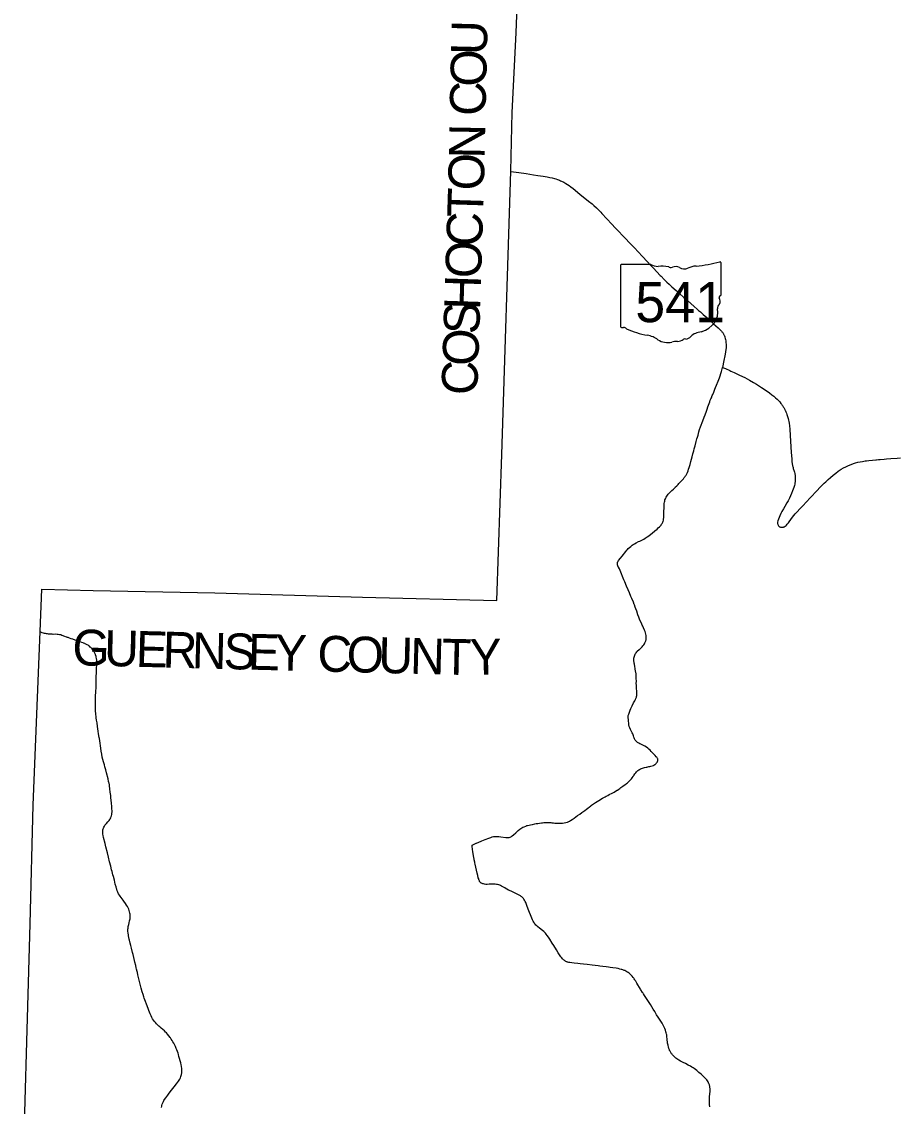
# Model space of a CAD drawing. Extents: x 2125567 to 2397567, y 653347 to 829347.
# Drawn here: x 2186978 to 2211403, y 770418 to 800656 of the extents above; entities that cross this region are included whole.
import ezdxf

# ---------------------------------------------------------------- set-up
doc = ezdxf.new("R2010")
doc.units = 0
for name, color, linetype in [('GM_X_County', 7, 'Continuous'), ('GM_X_County_Text', 7, 'Continuous'), ('GM_X_State_Location', 7, 'Continuous'), ('GM_X_State_Route', 7, 'Continuous'), ('GM_X_State_Shield', 7, 'Continuous')]:
    doc.layers.add(name, color=color, linetype=linetype)

msp = doc.modelspace()

# ---------------------------------------------------------------- linework, layer by layer
at = {"layer": 'GM_X_County'}
msp.add_lwpolyline([(2186978, 767293), (2187218, 775508), (2187296, 778812), (2187489, 783655), (2187543, 784833), (2188969, 784801), (2192356, 784732), (2196471, 784613), (2200213, 784515), (2200352, 788594), (2200607, 796487), (2200640, 798126), (2200752, 800346), (2200989, 806420)], dxfattribs=at)
at = {"layer": 'GM_X_State_Route'}
for points in [[(2200608, 796484), (2200827, 796452), (2201034, 796420), (2201242, 796389), (2201359, 796372), (2201512, 796349), (2201618, 796331), (2201696, 796316), (2201757, 796302), (2201820, 796284), (2201861, 796272), (2201905, 796257), (2201934, 796247), (2201963, 796235), (2201995, 796221), (2202023, 796208), (2202082, 796178), (2202137, 796147), (2202187, 796117), (2202234, 796086), (2202279, 796053), (2202347, 796001), (2202533, 795850), (2202772, 795655), (2202871, 795574), (2202918, 795533), (2202990, 795465), (2203039, 795417), (2203085, 795371), (2203110, 795345), (2203146, 795307), (2203420, 795015), (2203517, 794912), (2203626, 794798), (2203713, 794705), (2203811, 794599), (2203901, 794503), (2204048, 794349), (2204150, 794242), (2204271, 794113), (2204404, 793972), (2204500, 793868), (2204578, 793784), (2204675, 793682), (2204769, 793582), (2204792, 793558), (2204879, 793469), (2204956, 793393), (2205020, 793335), (2205026, 793329), (2205094, 793267), (2205212, 793163), (2205305, 793080), (2205426, 792970), (2205527, 792881), (2205618, 792801), (2205712, 792718), (2205796, 792645), (2205840, 792606), (2205887, 792565), (2205965, 792496), (2206069, 792405), (2206169, 792315), (2206256, 792235), (2206385, 792119), (2206394, 792110), (2206430, 792075), (2206464, 792040), (2206477, 792026), (2206488, 792012), (2206500, 791997), (2206510, 791983), (2206519, 791970), (2206528, 791956), (2206536, 791943), (2206542, 791929), (2206550, 791913), (2206558, 791896), (2206561, 791888)], [(2206561, 791888), (2206565, 791880), (2206571, 791862), (2206581, 791828), (2206589, 791799), (2206596, 791756), (2206602, 791711), (2206605, 791658), (2206605, 791633), (2206605, 791608), (2206603, 791566), (2206597, 791513), (2206589, 791454), (2206577, 791390), (2206530, 791165), (2206511, 791059), (2206504, 791019)], [(2204051, 784396), (2204046, 784409), (2204022, 784470), (2203977, 784572), (2203950, 784635), (2203911, 784733), (2203876, 784818), (2203831, 784920), (2203780, 785037), (2203757, 785095), (2203721, 785186), (2203693, 785262), (2203671, 785313), (2203652, 785354), (2203630, 785399), (2203606, 785445), (2203600, 785455), (2203596, 785464), (2203592, 785474), (2203588, 785483), (2203585, 785493), (2203584, 785499), (2203581, 785509), (2203579, 785522), (2203578, 785530), (2203577, 785542), (2203577, 785550), (2203578, 785561), (2203580, 785572), (2203581, 785578), (2203583, 785586), (2203586, 785592), (2203590, 785602), (2203594, 785610), (2203600, 785620), (2203609, 785632), (2203665, 785701), (2203705, 785751), (2203744, 785801), (2203770, 785835), (2203810, 785890), (2203838, 785925), (2203856, 785945), (2203879, 785966), (2203909, 785994), (2203948, 786026), (2203988, 786058), (2204018, 786079), (2204054, 786101), (2204103, 786127), (2204163, 786161), (2204200, 786178), (2204253, 786203), (2204312, 786234), (2204346, 786254), (2204373, 786272), (2204403, 786291), (2204451, 786326), (2204505, 786371), (2204542, 786401), (2204617, 786460), (2204680, 786512), (2204716, 786543), (2204745, 786570), (2204769, 786596), (2204791, 786622), (2204807, 786646), (2204823, 786670), (2204832, 786684), (2204839, 786699), (2204845, 786714), (2204850, 786726), (2204858, 786757), (2204864, 786789), (2204870, 786831), (2204871, 786875), (2204873, 786929), (2204874, 786992), (2204875, 787115), (2204879, 787185), (2204883, 787221), (2204888, 787259), (2204894, 787291), (2204902, 787322), (2204912, 787352), (2204924, 787379), (2204937, 787405), (2204952, 787429), (2204969, 787453), (2204992, 787480), (2205019, 787509), (2205096, 787585), (2205136, 787623), (2205146, 787632), (2205157, 787644), (2205174, 787659), (2205190, 787675), (2205230, 787714), (2205249, 787732), (2205271, 787756), (2205291, 787778), (2205309, 787797), (2205318, 787806), (2205369, 787861), (2205393, 787888), (2205416, 787916), (2205441, 787947), (2205460, 787974), (2205473, 787993), (2205481, 788005), (2205488, 788018), (2205499, 788036), (2205508, 788051), (2205516, 788068), (2205527, 788091), (2205544, 788134), (2205560, 788177), (2205576, 788228), (2205584, 788255), (2205602, 788315), (2205622, 788391), (2205657, 788523), (2205681, 788609), (2205703, 788690), (2205718, 788744), (2205742, 788834), (2205774, 788954), (2205792, 789025), (2205805, 789072), (2205822, 789130), (2205848, 789219), (2205868, 789287), (2205895, 789361), (2205957, 789527), (2205996, 789633), (2206018, 789696), (2206055, 789799), (2206074, 789851), (2206098, 789916), (2206116, 789965), (2206132, 790013), (2206147, 790055), (2206165, 790100), (2206181, 790139), (2206195, 790173), (2206219, 790233), (2206233, 790267), (2206259, 790330), (2206269, 790354), (2206279, 790379), (2206292, 790409), (2206311, 790457), (2206340, 790526), (2206383, 790631), (2206399, 790677), (2206419, 790731), (2206437, 790786), (2206458, 790852), (2206472, 790901), (2206494, 790980), (2206504, 791019)], [(2206504, 791019), (2206587, 790986), (2206711, 790930), (2206739, 790917), (2206831, 790873), (2206982, 790801), (2207124, 790733), (2207192, 790699), (2207261, 790662), (2207369, 790600), (2207448, 790552), (2207588, 790460), (2207749, 790353), (2207817, 790306), (2207883, 790257), (2207936, 790213), (2207984, 790173), (2208027, 790132), (2208064, 790095), (2208099, 790055), (2208132, 790014), (2208146, 789996), (2208160, 789978), (2208173, 789959), (2208185, 789940), (2208198, 789921), (2208212, 789899), (2208222, 789882), (2208231, 789865), (2208242, 789845), (2208249, 789830), (2208255, 789817), (2208261, 789803), (2208271, 789779), (2208285, 789745), (2208300, 789705), (2208318, 789652), (2208335, 789596), (2208348, 789548), (2208357, 789506), (2208364, 789460), (2208373, 789392), (2208380, 789300), (2208392, 789117), (2208402, 788963), (2208422, 788642), (2208433, 788465), (2208439, 788393), (2208447, 788328), (2208454, 788287), (2208456, 788276)], [(2208456, 788276), (2208461, 788255), (2208470, 788224), (2208477, 788202), (2208504, 788125), (2208513, 788096), (2208521, 788061), (2208524, 788044), (2208527, 788027), (2208528, 788010), (2208530, 787992), (2208531, 787949), (2208530, 787890), (2208527, 787834), (2208522, 787792), (2208517, 787759), (2208509, 787727), (2208492, 787673), (2208458, 787574), (2208430, 787500), (2208402, 787434), (2208376, 787377), (2208354, 787336), (2208335, 787302), (2208300, 787246), (2208239, 787142), (2208200, 787074), (2208162, 787004), (2208130, 786942), (2208102, 786880), (2208083, 786834), (2208066, 786789), (2208048, 786736), (2208041, 786706), (2208039, 786681), (2208040, 786665), (2208042, 786651), (2208044, 786644), (2208048, 786634), (2208053, 786622), (2208064, 786604), (2208077, 786589), (2208086, 786582), (2208095, 786576), (2208105, 786571), (2208120, 786565), (2208139, 786562), (2208159, 786560), (2208188, 786563), (2208194, 786564), (2208207, 786568), (2208218, 786571), (2208227, 786575), (2208252, 786591), (2208274, 786607), (2208290, 786621), (2208308, 786644), (2208341, 786686), (2208429, 786807), (2208490, 786885), (2208532, 786935), (2208582, 786992), (2208661, 787076), (2208740, 787159), (2208946, 787380), (2209145, 787589), (2209220, 787667), (2209291, 787740), (2209340, 787789), (2209385, 787832), (2209453, 787893), (2209514, 787948), (2209589, 788012), (2209663, 788072), (2209729, 788121), (2209815, 788177), (2209877, 788214), (2209938, 788245), (2210016, 788281), (2210089, 788311), (2210154, 788335), (2210213, 788354), (2210273, 788372), (2210341, 788387), (2210405, 788399), (2210477, 788410), (2210516, 788415), (2210581, 788422), (2210686, 788433), (2210781, 788441), (2210792, 788442), (2210849, 788446), (2210902, 788450), (2211013, 788460), (2211078, 788465), (2211193, 788474), (2211376, 788486), (2211467, 788494)], [(2204202, 783166), (2204210, 783173), (2204236, 783198), (2204262, 783228), (2204286, 783258), (2204310, 783288), (2204329, 783314), (2204343, 783339), (2204354, 783359), (2204361, 783374), (2204367, 783391), (2204370, 783405), (2204374, 783421), (2204378, 783447), (2204380, 783477), (2204379, 783514), (2204377, 783543), (2204370, 783579), (2204361, 783615), (2204348, 783652), (2204334, 783690), (2204303, 783760), (2204283, 783807), (2204268, 783835), (2204243, 783889), (2204214, 783953), (2204193, 784000), (2204171, 784058), (2204149, 784116), (2204115, 784220), (2204091, 784285), (2204073, 784338), (2204051, 784396)], [(2189061, 782905), (2189054, 782939), (2189050, 782955), (2189042, 782982), (2189037, 782998), (2189031, 783015), (2189017, 783048), (2188998, 783090), (2188988, 783108), (2188976, 783127), (2188962, 783146), (2188943, 783168), (2188925, 783187), (2188913, 783199), (2188901, 783210), (2188888, 783223), (2188864, 783243), (2188844, 783258), (2188825, 783270), (2188805, 783283), (2188786, 783295), (2188766, 783305), (2188750, 783314), (2188737, 783320), (2188703, 783334), (2188689, 783339), (2188652, 783352), (2188602, 783370), (2188553, 783386), (2188510, 783402), (2188467, 783417), (2188402, 783439), (2188358, 783454), (2188310, 783470), (2188272, 783484), (2188253, 783491), (2188238, 783496), (2188227, 783500), (2188180, 783517), (2188153, 783528), (2188132, 783537), (2188100, 783548), (2188064, 783558), (2188029, 783567), (2187992, 783573), (2187962, 783576), (2187911, 783577), (2187856, 783576), (2187823, 783577), (2187797, 783578), (2187757, 783580), (2187723, 783584), (2187695, 783587), (2187666, 783592), (2187636, 783599), (2187610, 783604), (2187583, 783611), (2187548, 783622), (2187525, 783629), (2187506, 783637), (2187490, 783652)], [(2204041, 782801), (2204038, 782821), (2204035, 782856), (2204035, 782878), (2204038, 782911), (2204044, 782942), (2204050, 782968), (2204060, 782995), (2204072, 783021), (2204083, 783041), (2204097, 783062), (2204114, 783084), (2204131, 783103), (2204185, 783152), (2204202, 783166)], [(2189142, 780669), (2189137, 780702), (2189122, 780807), (2189111, 780881), (2189101, 780945), (2189092, 781011), (2189077, 781110), (2189066, 781180), (2189056, 781248), (2189052, 781283), (2189044, 781344), (2189042, 781372), (2189036, 781434), (2189031, 781516), (2189030, 781607), (2189031, 781691), (2189035, 781772), (2189038, 781871), (2189042, 781956), (2189045, 782014), (2189048, 782066), (2189050, 782117), (2189051, 782166), (2189052, 782211), (2189053, 782285), (2189055, 782354), (2189057, 782429), (2189059, 782477), (2189060, 782522), (2189063, 782587), (2189064, 782617), (2189069, 782745), (2189070, 782811), (2189068, 782847), (2189067, 782860), (2189061, 782905)], [(2204102, 782202), (2204104, 782273), (2204103, 782347), (2204102, 782380), (2204101, 782413), (2204098, 782446), (2204095, 782472), (2204082, 782560), (2204075, 782602), (2204070, 782634), (2204064, 782667), (2204059, 782696), (2204054, 782721), (2204049, 782747), (2204045, 782773), (2204042, 782789), (2204041, 782801)], [(2206153, 770405), (2206146, 770471), (2206142, 770518), (2206141, 770561), (2206140, 770616), (2206143, 770673), (2206153, 770773), (2206158, 770822), (2206159, 770859), (2206160, 770894), (2206159, 770910), (2206154, 770955), (2206150, 770977), (2206146, 770994), (2206139, 771019), (2206134, 771032), (2206128, 771047), (2206116, 771075), (2206103, 771100), (2206082, 771131), (2206065, 771156), (2206044, 771181), (2206013, 771214), (2205976, 771250), (2205935, 771288), (2205907, 771312), (2205847, 771365), (2205788, 771416), (2205755, 771442), (2205719, 771470), (2205686, 771493), (2205650, 771514), (2205615, 771533), (2205549, 771568), (2205471, 771608), (2205411, 771640), (2205336, 771678), (2205290, 771703), (2205259, 771723), (2205229, 771743), (2205203, 771763), (2205163, 771800), (2205138, 771823), (2205113, 771851), (2205099, 771868), (2205088, 771882), (2205073, 771903), (2205063, 771918), (2205043, 771952), (2205032, 771974), (2205024, 771991), (2205015, 772011), (2205010, 772027), (2205006, 772038), (2205001, 772056), (2204998, 772070), (2204987, 772121), (2204976, 772179), (2204973, 772200), (2204963, 772284), (2204954, 772370), (2204949, 772409), (2204945, 772432), (2204938, 772468), (2204930, 772499), (2204917, 772543), (2204902, 772584), (2204882, 772627), (2204852, 772683), (2204820, 772737), (2204786, 772788), (2204749, 772846), (2204713, 772903), (2204670, 772969), (2204615, 773058), (2204573, 773124), (2204494, 773252), (2204401, 773400), (2204333, 773509), (2204306, 773550), (2204292, 773572), (2204278, 773595), (2204232, 773663), (2204216, 773687), (2204189, 773729), (2204141, 773805), (2204119, 773848), (2204105, 773872), (2204088, 773903), (2204075, 773924), (2204062, 773945), (2204045, 773970), (2204032, 773988), (2204012, 774013), (2203987, 774044), (2203959, 774075), (2203934, 774100), (2203903, 774126), (2203872, 774149), (2203837, 774171), (2203808, 774186), (2203779, 774200), (2203764, 774207), (2203732, 774219), (2203700, 774230), (2203685, 774235), (2203648, 774245), (2203596, 774256), (2203537, 774267), (2203453, 774280), (2203375, 774290), (2203330, 774295), (2203267, 774303), (2203167, 774315), (2203088, 774324), (2203036, 774330), (2202876, 774351), (2202733, 774368), (2202630, 774380), (2202537, 774390), (2202473, 774396), (2202368, 774407), (2202306, 774415), (2202251, 774424), (2202219, 774431), (2202197, 774437), (2202188, 774440), (2202168, 774447), (2202160, 774450), (2202142, 774459), (2202134, 774463), (2202113, 774475), (2202095, 774489), (2202075, 774506), (2202049, 774530), (2202027, 774555), (2202002, 774586), (2201983, 774613), (2201930, 774696), (2201878, 774780), (2201806, 774897), (2201760, 774969), (2201693, 775078), (2201673, 775108), (2201653, 775138), (2201621, 775183), (2201593, 775219), (2201574, 775242), (2201554, 775262), (2201525, 775288), (2201488, 775318), (2201401, 775384), (2201356, 775421), (2201327, 775446), (2201304, 775470), (2201284, 775492), (2201271, 775510), (2201267, 775516), (2201262, 775523), (2201251, 775540), (2201244, 775551), (2201231, 775576), (2201212, 775616), (2201192, 775667), (2201093, 775913), (2201053, 776014), (2201020, 776096), (2201006, 776129), (2200999, 776144), (2200987, 776167), (2200973, 776191), (2200960, 776210), (2200952, 776219), (2200935, 776240), (2200915, 776258), (2200897, 776272), (2200875, 776286), (2200842, 776305), (2200765, 776342), (2200694, 776375), (2200614, 776413), (2200546, 776446), (2200499, 776470), (2200479, 776481), (2200436, 776505), (2200388, 776533), (2200351, 776555), (2200320, 776571), (2200296, 776581), (2200269, 776591), (2200237, 776600), (2200205, 776606), (2200174, 776610), (2200137, 776611), (2200066, 776610), (2200003, 776607), (2199946, 776606), (2199911, 776606), (2199869, 776611), (2199845, 776616), (2199829, 776620), (2199807, 776629), (2199791, 776637), (2199782, 776643), (2199773, 776650), (2199763, 776658), (2199752, 776670), (2199745, 776678), (2199738, 776690), (2199729, 776705), (2199722, 776722), (2199717, 776735), (2199711, 776756), (2199701, 776791), (2199689, 776850), (2199673, 776920), (2199654, 777000), (2199633, 777087), (2199622, 777131), (2199617, 777153), (2199600, 777225), (2199586, 777289), (2199583, 777308), (2199566, 777402), (2199545, 777525), (2199538, 777578), (2199534, 777607), (2199531, 777642), (2199529, 777665), (2199527, 777700), (2199583, 777725), (2199603, 777735), (2199626, 777746), (2199641, 777752), (2199651, 777756), (2199672, 777763), (2199696, 777774), (2199802, 777816), (2199894, 777852), (2199997, 777894), (2200053, 777916), (2200090, 777928), (2200126, 777937), (2200148, 777941), (2200172, 777944), (2200211, 777944), (2200274, 777938), (2200332, 777931), (2200468, 777912), (2200501, 777909), (2200523, 777909), (2200546, 777911), (2200564, 777914), (2200586, 777921), (2200606, 777930), (2200625, 777941), (2200646, 777957), (2200684, 777988), (2200742, 778041), (2200751, 778050), (2200773, 778070), (2200792, 778088), (2200815, 778107), (2200858, 778143), (2200885, 778162), (2200913, 778179), (2200945, 778197), (2200975, 778211), (2201020, 778231), (2201039, 778238), (2201057, 778244), (2201073, 778249), (2201114, 778259), (2201159, 778269), (2201208, 778279), (2201275, 778293), (2201315, 778299), (2201356, 778306), (2201401, 778313), (2201463, 778320), (2201489, 778323), (2201528, 778327), (2201544, 778329), (2201570, 778330), (2201596, 778331), (2201635, 778333), (2201655, 778334), (2201685, 778333), (2201707, 778331), (2201724, 778329), (2201753, 778325), (2201792, 778321), (2201834, 778315), (2201876, 778311), (2201912, 778308), (2201954, 778308), (2202000, 778311), (2202045, 778316), (2202097, 778324), (2202142, 778333), (2202182, 778344), (2202219, 778358), (2202245, 778371), (2202270, 778385), (2202311, 778412), (2202373, 778455), (2202466, 778523), (2202527, 778567), (2202583, 778606), (2202612, 778628), (2202665, 778666), (2202718, 778705), (2202752, 778731), (2202759, 778737), (2202790, 778762), (2202837, 778798), (2202852, 778810), (2202907, 778851), (2202934, 778870), (2202962, 778888), (2203009, 778917), (2203063, 778948), (2203165, 779008), (2203235, 779049), (2203261, 779063), (2203305, 779086), (2203351, 779110), (2203427, 779148), (2203482, 779177), (2203522, 779200), (2203566, 779228), (2203577, 779235), (2203615, 779260), (2203644, 779281), (2203673, 779303), (2203699, 779323), (2203726, 779342), (2203762, 779369), (2203807, 779403), (2203830, 779420), (2203856, 779440), (2203899, 779476), (2203913, 779489), (2203945, 779522), (2203966, 779547), (2203989, 779578), (2204016, 779615), (2204028, 779634), (2204031, 779640), (2204065, 779689), (2204085, 779715), (2204106, 779741), (2204129, 779765), (2204146, 779780), (2204172, 779801), (2204192, 779812), (2204216, 779824), (2204250, 779838), (2204279, 779847), (2204333, 779861), (2204378, 779872), (2204397, 779876), (2204451, 779889), (2204454, 779889), (2204479, 779896), (2204508, 779903), (2204549, 779913), (2204579, 779924), (2204594, 779931), (2204616, 779943), (2204636, 779959), (2204653, 779974), (2204670, 779994), (2204681, 780009), (2204690, 780023), (2204697, 780037), (2204703, 780052), (2204705, 780066), (2204706, 780075), (2204706, 780085), (2204705, 780090), (2204703, 780098), (2204699, 780107), (2204693, 780118), (2204686, 780129), (2204673, 780148), (2204658, 780165), (2204632, 780194), (2204581, 780249), (2204517, 780313), (2204487, 780343), (2204452, 780376), (2204420, 780404), (2204387, 780430), (2204345, 780455), (2204302, 780478), (2204232, 780512), (2204199, 780528), (2204170, 780542), (2204135, 780563), (2204127, 780568), (2204097, 780595), (2204073, 780626), (2204055, 780665), (2204044, 780692), (2204037, 780710), (2204025, 780744), (2204011, 780777), (2204002, 780798), (2203988, 780827), (2203980, 780845), (2203942, 780924), (2203921, 780967), (2203908, 781005), (2203897, 781053), (2203891, 781102), (2203887, 781154), (2203883, 781199), (2203880, 781248), (2203878, 781281), (2203880, 781310), (2203891, 781352), (2203909, 781405), (2203932, 781465), (2203950, 781510), (2203967, 781550), (2203985, 781587), (2204027, 781664), (2204062, 781724), (2204079, 781758), (2204083, 781766), (2204099, 781805), (2204104, 781824), (2204111, 781846), (2204115, 781872), (2204117, 781897), (2204118, 781933), (2204114, 781999), (2204110, 782054), (2204104, 782161), (2204102, 782202)], [(2191439, 771476), (2191438, 771485), (2191433, 771515), (2191430, 771534), (2191420, 771576), (2191407, 771634), (2191360, 771809), (2191345, 771861), (2191334, 771902), (2191320, 771946), (2191303, 771992), (2191286, 772032), (2191262, 772086), (2191243, 772123), (2191218, 772174), (2191192, 772219), (2191173, 772250), (2191145, 772292), (2191119, 772329), (2191111, 772339), (2191078, 772381), (2191038, 772429), (2191008, 772463), (2190985, 772487), (2190953, 772519), (2190866, 772596), (2190824, 772632), (2190803, 772651), (2190766, 772686), (2190735, 772719), (2190703, 772755), (2190678, 772786), (2190650, 772823), (2190626, 772860), (2190608, 772891), (2190582, 772941), (2190556, 773000), (2190537, 773046), (2190519, 773092), (2190499, 773143), (2190453, 773266), (2190427, 773338), (2190392, 773434), (2190380, 773470), (2190360, 773531), (2190337, 773613), (2190310, 773711), (2190261, 773902), (2190215, 774084), (2190201, 774147), (2190193, 774176), (2190178, 774246), (2190171, 774275), (2190156, 774341), (2190134, 774440), (2190123, 774484), (2190103, 774564), (2190083, 774647), (2190066, 774710), (2190037, 774828), (2190018, 774902), (2190001, 774969), (2189982, 775050), (2189976, 775074), (2189965, 775128), (2189955, 775172), (2189949, 775202), (2189941, 775249), (2189934, 775298), (2189933, 775328), (2189935, 775354), (2189940, 775389), (2189948, 775433), (2189960, 775487), (2189971, 775532), (2189985, 775592), (2189996, 775643), (2189998, 775676), (2190000, 775703), (2190000, 775738), (2189998, 775773), (2189992, 775805), (2189985, 775838), (2189975, 775875), (2189961, 775911), (2189945, 775948), (2189925, 775986), (2189899, 776029), (2189868, 776075), (2189825, 776137), (2189803, 776165), (2189773, 776204), (2189748, 776238), (2189724, 776273), (2189701, 776309), (2189678, 776345), (2189659, 776384), (2189639, 776429), (2189625, 776471), (2189619, 776487), (2189606, 776536), (2189585, 776615), (2189559, 776726), (2189533, 776825), (2189521, 776871), (2189509, 776915), (2189496, 776964), (2189483, 777013), (2189458, 777115), (2189427, 777234), (2189394, 777364), (2189365, 777484), (2189322, 777651), (2189299, 777745), (2189260, 777910), (2189248, 777969), (2189241, 778005), (2189237, 778035), (2189235, 778059), (2189235, 778070), (2189236, 778093), (2189240, 778122), (2189249, 778153), (2189257, 778177), (2189269, 778204), (2189281, 778227), (2189298, 778253), (2189319, 778281), (2189338, 778303), (2189381, 778348), (2189413, 778385), (2189434, 778415), (2189445, 778435), (2189460, 778465), (2189472, 778496), (2189478, 778517), (2189486, 778553), (2189491, 778586), (2189494, 778625), (2189495, 778665), (2189493, 778705), (2189487, 778780), (2189478, 778871), (2189470, 778955), (2189464, 779020), (2189458, 779080), (2189447, 779180), (2189435, 779269), (2189424, 779349), (2189420, 779377), (2189412, 779424), (2189408, 779446), (2189400, 779478), (2189384, 779545), (2189340, 779716), (2189319, 779798), (2189296, 779880), (2189280, 779936), (2189257, 780019), (2189238, 780089), (2189224, 780150), (2189206, 780237), (2189193, 780318), (2189180, 780399), (2189150, 780607), (2189142, 780669)], [(2190875, 770387), (2190879, 770420), (2190884, 770445), (2190895, 770480), (2190907, 770514), (2190924, 770549), (2190940, 770577), (2190961, 770610), (2190996, 770659), (2191018, 770690), (2191045, 770727), (2191070, 770759), (2191115, 770819), (2191151, 770864), (2191191, 770914), (2191227, 770960), (2191294, 771046), (2191348, 771120), (2191367, 771148), (2191382, 771174), (2191402, 771215), (2191415, 771247), (2191425, 771275), (2191433, 771307), (2191440, 771347), (2191442, 771377), (2191444, 771404), (2191443, 771435), (2191440, 771466), (2191439, 771476)]]:
    msp.add_lwpolyline(points, dxfattribs=at)
at = {"layer": 'GM_X_State_Shield'}
for p, q in [((2203661, 793860), (2203661, 792159)), ((2204510, 793889), (2203689, 793889)), ((2206463, 793042), (2206463, 793932)), ((2206463, 793042), (2206463, 793042))]:
    msp.add_line(p, q, dxfattribs=at)
for centre, major_axis, start_param, end_param in [((2203694, 793864), (32.5, 0), 1.712693, 3.28349), ((2204705, 794087), (315, 0), 4.042523, 4.731795), ((2204809, 792934), (1130, 0), 1.404758, 1.657858), ((2205066, 793873), (90.8, 0), 3.836095, 5.185415), ((2205199, 793676), (189, 0), 0.950623, 2.079405), ((2205443, 793946), (227, 0), 4.081561, 5.145723), ((2205844, 793370), (598, 0), 1.699011, 2.107814), ((2205465, 796209), (2971, 0), 4.814394, 5.042369), ((2206432, 793935), (31.2, 0), 6.141152, 7.989035), ((2206456, 792976), (48.3, 0), 1.883978, 3.671073), ((2206149, 792864), (290, 0), 5.934695, 6.695948), ((2206430, 793038), (33.4, 0), 5.05454, 6.418171), ((2205632, 792556), (743, 0), 5.101752, 6.440018), ((2206575, 792669), (211, 0), 2.387724, 3.262537), ((2203694, 792155), (32.7, 0), 3.00124, 4.508301), ((2203699, 792329), (250, 0), 4.665946, 4.897461), ((2203750, 792061), (90.1, 0), 0.519207, 1.627899), ((2204888, 793589), (2146, 0), 4.195997, 4.488961), ((2205945, 791681), (407, 0), 1.647645, 2.488434), ((2204248, 791395), (671, 0), 0.823519, 1.323587), ((2204974, 792052), (426, 0), 4.026481, 4.996735), ((2205220, 791464), (350, 0), 1.495662, 1.94098), ((2205251, 791925), (227, 0), 4.691044, 5.507374), ((2205456, 791760), (63.9, 0), 1.147584, 2.315152), ((2205429, 791994), (240, 0), 4.937069, 5.64225)]:
    msp.add_ellipse(centre, major_axis=major_axis, ratio=0.8, start_param=start_param, end_param=end_param, dxfattribs=at)

# ---------------------------------------------------------------- texts
at = {"layer": 'GM_X_County_Text'}
for s, rotation, p in [('U', 88.6368, (2199938, 799717)), ('O', 88.6499, (2199918, 798835)), ('C', 88.7376, (2199900, 798020)), ('N', 88.9622, (2199878, 796833)), ('O', 88.469, (2199854, 795941)), ('T', 88.2126, (2199831, 795190)), ('C', 88.1616, (2199804, 794374)), ('O', 88.1583, (2199776, 793492)), ('H', 88.1594, (2199748, 792610)), ('S', 88.159, (2199726, 791931)), ('O', 88.1594, (2199698, 791048)), ('C', 88.1594, (2199671, 790234)), ('G', 358.5416, (2188380, 782718)), ('U', 358.5422, (2189264, 782696)), ('E', 358.5419, (2190148, 782673)), ('R', 358.5416, (2190896, 782654)), ('N', 358.5427, (2191710, 782633)), ('S', 358.5408, (2192594, 782611)), ('E', 358.5423, (2193271, 782594)), ('Y', 358.5417, (2194019, 782575)), ('C', 358.5413, (2195207, 782544)), ('O', 358.5414, (2196021, 782524)), ('U', 358.5421, (2196905, 782501)), ('N', 358.5446, (2197789, 782479)), ('T', 358.7696, (2198677, 782456)), ('Y', 1.3227, (2199474, 782440))]:
    msp.add_text(s, height=1000, rotation=rotation, dxfattribs=at).set_placement(p)
at = {"layer": 'GM_X_State_Location'}
for s, p in [('541', (2205258, 792442)), ('662', (2188903, 777974)), ('658', (2201588, 774498))]:
    msp.add_text(s, height=1, rotation=0, dxfattribs=at).set_placement(p)
for s, p in [('s', (2205611, 792514)), ('r', (2205611, 792514)), ('s', (2189256, 778047)), ('r', (2189256, 778047)), ('s', (2201941, 774571)), ('r', (2201941, 774571))]:
    msp.add_text(s, height=1, dxfattribs=at).set_placement(p)
at = {"layer": 'GM_X_State_Shield'}
msp.add_text('541', height=1120.7, dxfattribs=at).set_placement((2204074, 792279))

doc.saveas('drawing.dxf')
